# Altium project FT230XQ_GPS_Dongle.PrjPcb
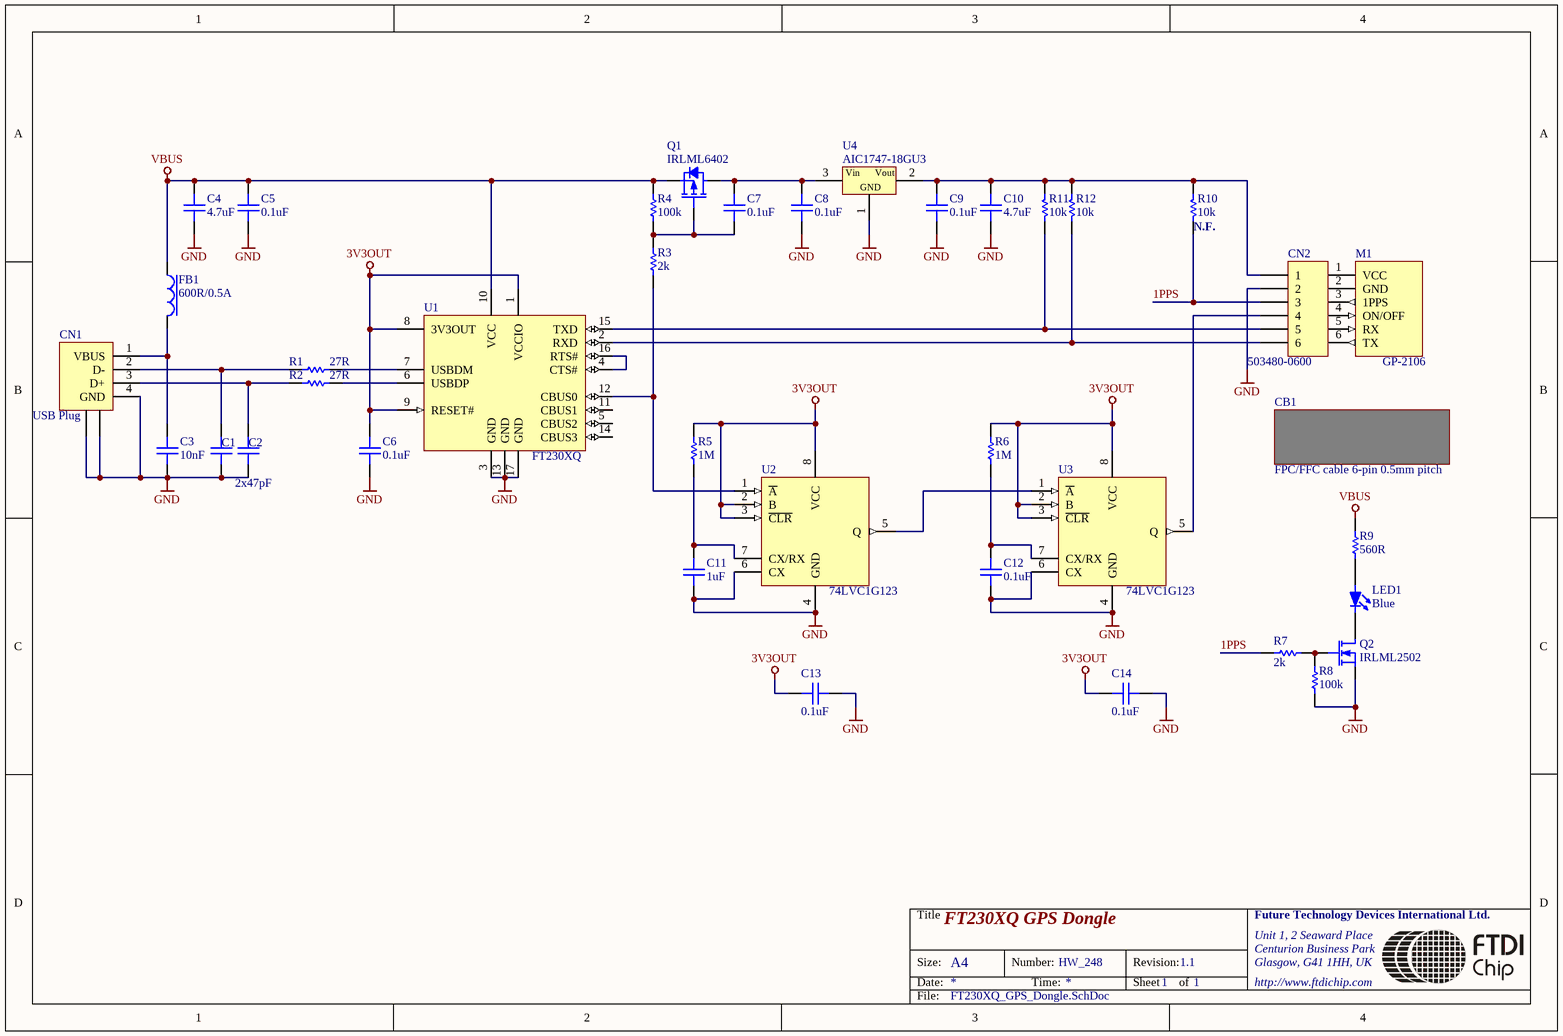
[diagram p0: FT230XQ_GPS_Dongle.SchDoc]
1 sheet, 38 parts. Net scope: global (net labels, ports and power ports of the same name join across sheets).
Board file: FT230XQ_GPS_Dongle.pcbdoc

## Sheet FT230XQ_GPS_Dongle.SchDoc: FT230XQ GPS Dongle
size A4; Author: P. Rybak; CompanyName: Future Technology Devices International Ltd.; DrawnBy: P. Rybak; Engineer: P. Rybak; Organization: Future Technology Devices International Ltd.; Address1: Unit 1, 2 Seaward Place; Address2: Centurion Business Park; Address3: Glasgow, G41 1HH, UK; Address4: http://www.ftdichip.com; DocumentNumber: HW_248; Revision: 1.1; SheetNumber: 1; SheetTotal: 1; PageSetup: Record=PageOptions|CenterHorizontal=True|CenterVertical=True|PrintScale=1.00|XCorrection=1.00|YCorrection=1.00|PrintKind=0|BorderSize=5000000|LeftOffset=0|BottomOffset=0|Orientation=2|PaperLength=1000|PaperWidth=1000|Scale=100|PaperSource=7|PrintQuality=-4|MediaType=1|DitherType=10|PaperKind=A4|PrintScaleMode=1

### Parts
C1  47pF  [CAPC1005-0402]  (value not drawn)
C2  47pF  [CAPC1005-0402]  (value not drawn)
C3  10nF  [CAPC1005-0402]
C4  4.7uF  [CAPC1608-0603]
C5  0.1uF  [CAPC1005-0402]
C6  0.1uF  [CAPC1005-0402]
C7  0.1uF  [CAPC1005-0402]
C8  0.1uF  [CAPC1005-0402]
C9  0.1uF  [CAPC1005-0402]
C10  4.7uF  [CAPC1608-0603]
C11  1uF  [CAPC1005-0402]
C12  0.1uF  [CAPC1005-0402]
C13  0.1uF  [CAPC1005-0402]
C14  0.1uF  [CAPC1005-0402]
CB1  FPC/FFC cable 6-pin 0.5mm pitch  (mechanical)
CN1  USB Plug  [CN_USB-PLUG A]
CN2  503480-0600  [CN_6Pin_FPC/FFC; 503480-0600 Molex]
FB1  600R/0.5A  [IND_C2012-0805]
LED1  Blue  [LEDC2012-0805]
M1  GP-2106  (mechanical)
Q1  IRLML6402  [SOT23-3AL]
Q2  IRLML2502  [SOT23-3AL]
R1  27R  [RESC1005-0402]
R2  27R  [RESC1005-0402]
R3  2k  [RESC1005-0402]
R4  100k  [RESC1005-0402]
R5  1M  [RESC1005-0402]
R6  1M  [RESC1005-0402]
R7  2k  [RESC1005-0402]
R8  100k  [RESC1005-0402]
R9  560R  [RESC1005-0402]
R10  10k  [RESC1005-0402]  (no BOM)
R11  10k  [RESC1005-0402]
R12  10k  [RESC1005-0402]
U1  FT230XQ  [VQFN65P400X400X90-16N]
U2  74LVC1G123  [BGA6C50P4X2_190X90X50]
U3  74LVC1G123  [BGA6C50P4X2_190X90X50]
U4  AIC1747-18GU3  [SOT23-3AL]

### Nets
3V3OUT: C6.1 C13.1 C14.1 R5.2 R6.2 U1.1(VCCIO) U1.8(3V3OUT) U1.9(RESET#) U2.2(B) U2.3(~{CLR}) U2.8(VCC) U3.2(B) U3.3(~{CLR}) U3.8(VCC)
GND: C1.2 C2.2 C3.2 C4.2 C5.2 C6.2 C8.2 C9.2 C10.2 C11.2 C12.2 C13.2 C14.2 CN1.4(GND) CN1.5(SHLD) CN1.6(SHLD) CN2.2 Q2.2(S) R8.1 U1.3(GND) U1.13(GND) U1.17(GND) U2.4(GND) U2.6(CX) U3.4(GND) U3.6(CX) U4.1(GND)
VBUS: C4.1 C5.1 FB1.1 Q1.2(S) R4.2 R9.2 U1.10(VCC)
1PPS: CN2.3 R7.2 R10.1
NetC1_1: C1.1 CN1.2(D-) R1.2
NetC2_1: C2.1 CN1.3(D+) R2.2
NetC3_1: C3.1 CN1.1(VBUS) FB1.2
NetC7_1: C7.1 C8.1 Q1.3(D) U4.3(VIN)
NetC7_2: C7.2 Q1.1(G) R3.2 R4.1
NetC9_1: C9.1 C10.1 CN2.1 R10.2 R11.2 R12.2 U4.2(VOUT)
NetC11_1: C11.1 R5.1 U2.7(CX/RX)
NetC12_1: C12.1 R6.1 U3.7(CX/RX)
NetCN2_4: CN2.4 U3.5(Q)
NetCN2_5: CN2.5 R11.1 U1.15(TXD)
NetCN2_6: CN2.6 R12.1 U1.2(RXD)
NetLED1_1: LED1.1(K) Q2.3(D)
NetLED1_2: LED1.2(A) R9.1
NetQ2_1: Q2.1(G) R7.1 R8.2
NetR1_1: R1.1 U1.7(USBDM)
NetR2_1: R2.1 U1.6(USBDP)
NetR3_1: R3.1 U1.12(CBUS0) U2.1(~{A})
NetU1_4: U1.4(CTS#) U1.16(RTS#)
NetU2_5: U2.5(Q) U3.1(~{A})

Not connected (* = marked no-connect by the designer): M1 1(VCC) 2(GND) 3(1PPS) 4(ON/OFF) 5(RX) 6(TX); U1 5(CBUS2) 11(CBUS1) 14(CBUS3)

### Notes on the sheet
- (near R10) N.F.
- 2x47pF

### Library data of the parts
C1 C2 = CAP_SEMI: Capacitor bipolar; Manufacturer: Yageo; ManufacturerPartNo: CC0402JRNPO9BN470; Note: CAP CER 47PF 50V 5% NPO 0402
C3 = CAP_SEMI: Capacitor bipolar; Manufacturer: Yageo; ManufacturerPartNo: CC0402KRX7R8BB103; Note: CAP CER 10000PF 25V 10% X7R 0402
C4 C10 = CAP_SEMI: Capacitor bipolar; Manufacturer: Kemet; ManufacturerPartNo: C0603C475K8PACTU; Note: CAP CER 4.7UF 10V 10% X5R 0603
C5-C9 C11-C14 = CAP_SEMI: Capacitor bipolar; Manufacturer: Yageo; ManufacturerPartNo: CC0402KRX7R6BB104; Note: CAP CER 0.1UF 10V 10% X7R 0402
CB1 = Cable_Ribbon_127_26: FPC/FFC cable; 6-pin; 0.5mm pitch; 30...70mm length; Note: 0.5mm pitch; 40mm min 50mm max lenght; FFC cable; 6-pin
CN1 = CN_USB: USB connector
CN2 = CN_HEADER 6: Header, 6-Pin; Manufacturer: Molex Inc; Note: CONN .5MM FPC 6POS RA SMD B-FLIP
FB1 = FERRITE_BEAD: Chip Ferrite Bead 0805; Manufacturer: TDK Corporation; ManufacturerPartNo: MMZ1608B601C; Note: FERRITE CHIP 600 OHM 500MA 0603
LED1 = D_LED: Typical LED diode; Manufacturer: OSRAM Opto Semiconductors Inc; ManufacturerPartNo: LB M673-L1N2-35-Z; Note: LED TOPLED 471NM BLUE CLR SMD
M1 = MOD_GP-2106_GPS: 48 Channel GP-2106 SiRF IV GPS Receiver; Manufacturer: ADH Technology Co. Ltd.; ManufacturerPartNo: GP-2106(SiRF Star IV); Note: Smart antenna GPS module with SiRFstar IV GPS solution.
Q1 = T_MOSFET-P: P-Channel MOSFET; SOT-23; Manufacturer: International Rectifier; ManufacturerPartNo: IRLML6402TRPBF; Note: MOSFET P-CH 20V 3.7A SOT-23
Q2 = T_MOSFET-N: N-Channel MOSFET; Manufacturer: International Rectifier; ManufacturerPartNo: IRLML2502TRPBF; Note: MOSFET N-CH 20V 4.2A SOT-23
R1 R2 = RES1: Resistor; Manufacturer: Yageo; ManufacturerPartNo: RC0402JR-0727RL; Note: RES 27 OHM 1/16W 5% 0402 SMD
R3 R7 = RES1: Resistor; Manufacturer: Yageo; ManufacturerPartNo: RC0402JR-072KL; Note: RES 2.0K OHM 1/16W 5% 0402 SMD
R4-R6 R10-R12 = RES1: Resistor; Manufacturer: Yageo; ManufacturerPartNo: RC0402JR-0710KL; Note: RES 10K OHM 1/16W 5% 0402 SMD
R8 = RES1: Resistor; Manufacturer: Yageo; ManufacturerPartNo: RC0402JR-07100KL; Note: RES 100K OHM 1/16W 5% 0402 SMD
R9 = RES1: Resistor; Manufacturer: Yageo; ManufacturerPartNo: RC0402JR-07560RL; Note: RES 560 OHM 1/16W 5% 0402 SMD
U1 = IC_FT230XQ: FT230XQ-QFN-16
U2 U3 = IC_74LVC1G123: Retriggerable Monostable Multivibrator; Manufacturer: Texas Instruments; ManufacturerPartNo: SN74LVC1G123YZPR; Note: IC SNGL RETRIG MULTIVIB 8-DSBGA
U4 = IC_AIC1722A: 300mA Low Dropout Linear Voltage Regulator; Analog Integration Corporation; Manufacturer: Analog Integrations Corporation; Note: 1.8V/300mA Linear Voltage Regulator; SOT23-3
